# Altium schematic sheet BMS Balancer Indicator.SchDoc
size A4; SheetNumber: 2; SheetTotal: 2
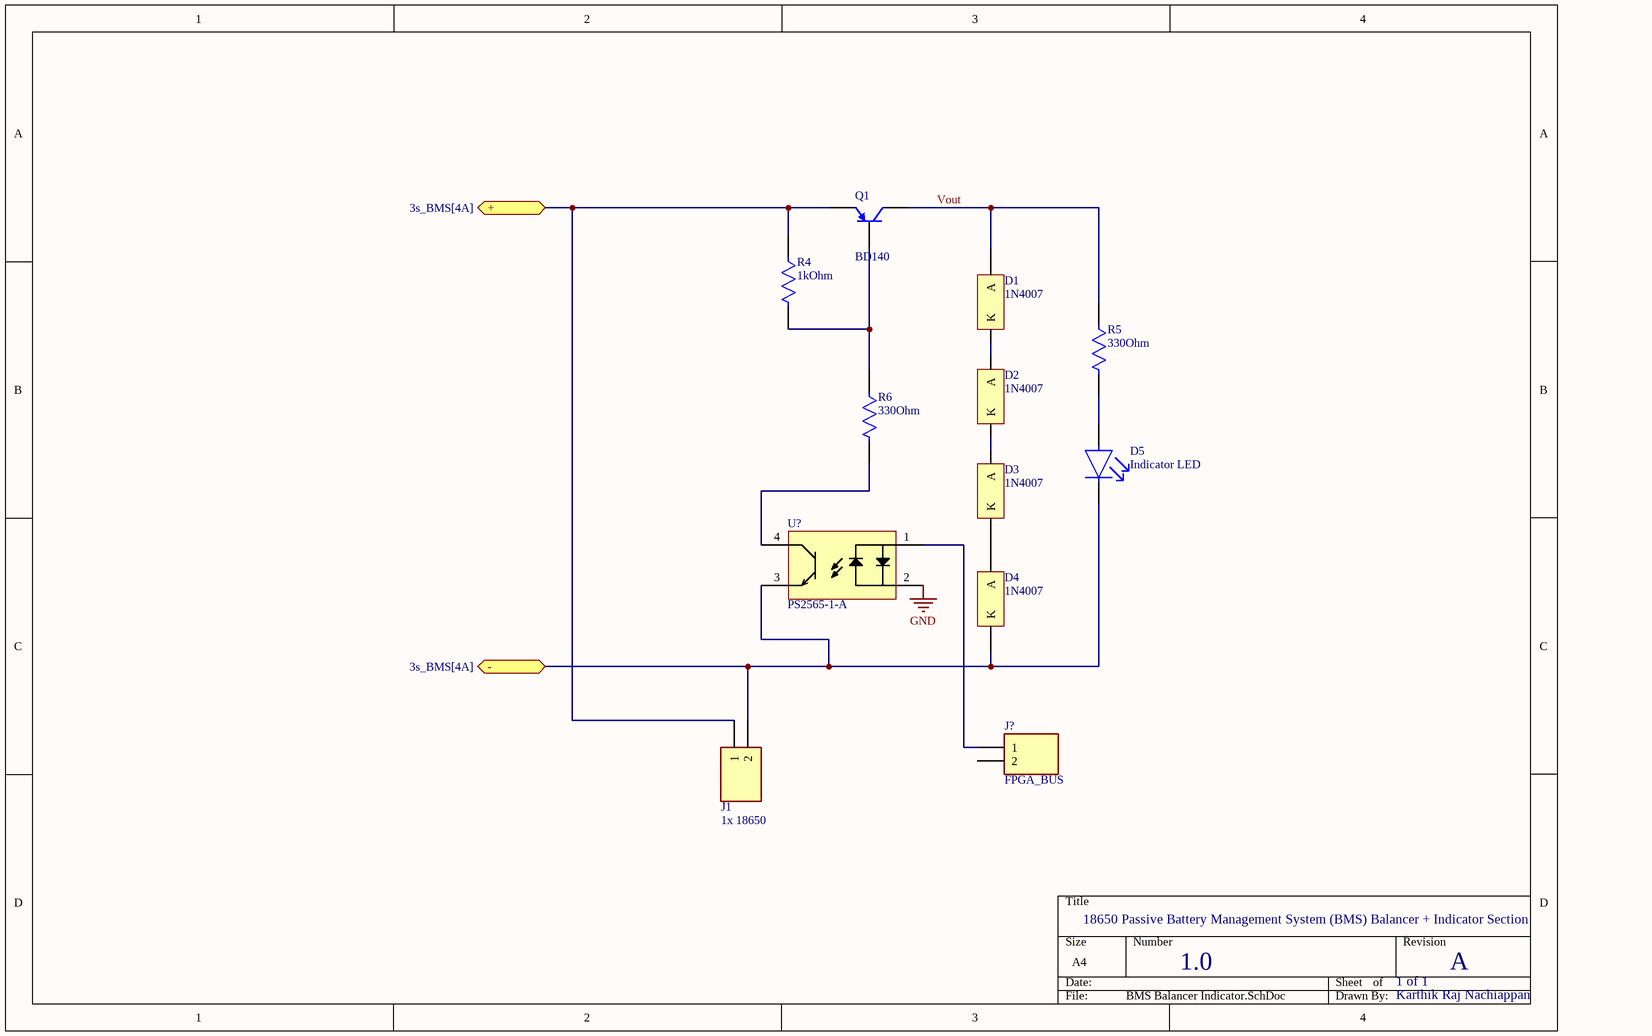
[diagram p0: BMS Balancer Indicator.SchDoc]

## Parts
D1  1N4007  [ONSC-AXIAL_LEAD-2-59-10_P]
D2  1N4007  [ONSC-AXIAL_LEAD-2-59-10_P]
D3  1N4007  [ONSC-AXIAL_LEAD-2-59-10_P]
D4  1N4007  [ONSC-AXIAL_LEAD-2-59-10_P]
D5  Indicator LED  [FP-HLMP-4700-MFG]
J1  1x 18650  [2828372]
J?  FPGA_BUS  [HDRV2W67P0X254_1X2_467X234X823P]
Q1  BD140  [ONSC-TO-225-3-77-09]
R4  1kOhm  [FP-MRS25-MFG]
R5  330Ohm  [FP-MRS25-MFG]
R6  330Ohm  [FP-MRS25-MFG]
U?  PS2565-1-A  [DIP762W50P254L460H455Q4B]

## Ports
+ (bidir, see 3s_BMS[4A]), - (bidir, see 3s_BMS[4A])

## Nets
GND: U?.2(Cathode)
+: J1.1 Q1.1(E) R4.1 ; port +
-: D4.1(K) D5.1(C) J1.2 U?.3(Emitter) ; port -
Vout: D1.2(A) Q1.2(C) R5.1
NetD1_1: D1.1(K) D2.2(A)
NetD2_1: D2.1(K) D3.2(A)
NetD3_1: D3.1(K) D4.2(A)
NetD5_2: D5.2(A) R5.2
NetJ?_1: J?.1 U?.1(Anode)
NetQ1_3: Q1.3(B) R4.2 R6.1
NetR6_2: R6.2 U?.4(Collector)

Not connected (* = marked no-connect by the designer): J? 2

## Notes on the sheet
- 18650 Passive Battery Management System (BMS) Balancer + Indicator Section
- 1.0
- 1 of 1
- A
- Karthik Raj Nachiappan

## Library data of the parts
D1-D4 = CMP-0902-00142-1: Standard Recovery Rectifier, 2-Pin Axial_Lead, Pb-Free, Bulk Bag; Manufacturer: On Semiconductor; IO(rec) Max (A): 1; IFSM Max (A): 30; VRRM Max (V): 1000
D5 = CMP-18399-000008-1: LED RED DIFFUSED T-1 3/4 T/H; Manufacturer: Broadcom; Luminous Intensity: 2.3mcd; Peak Emmision Wavelength: 635nm; Forward Voltage: 1.7V; Viewing Angle: 50°; Led Orientation: Straight; Reverse Voltage: 5V; Forward Current: 2mA; Power Dissipation: 14mW; Wavelength: 626nm
J1 = 282837-2: Connector; Manufacturer_Name: TE Connectivity
J? = 5-146277-2: Connector; Manufacturer_Name: TE Connectivity
Q1 = CMP-1048-00039-1: Plastic Medium-Power Silicon PNP Transistor, 3-Pin TO-225, Bulk Box; Manufacturer: On Semiconductor; IC Continuous (A): 1.5
R4-R6 = CMP-02408-000051-1: RES 1K OHM 0.6W 1% AXIAL; Power Rating: 600mW; Lead Diameter: 0.6mm; Voltage Rating (DC): 350V; Resistance: 1kR; Temperature Coefficient: 50ppm/°C
U? = CMP-00572-25674254-1: PS2565-1-A Optocoupler AC-IN 1-CH Transistor DC-OUT 4-Pin PDIP Magazine; Number of Elements: 1; Isolation Voltage: 5kV; Collector Emitter Voltage (VCEO): 300mV; Forward Current: 80mA; Output Current per Channel: 50mA; Output Voltage: 80V; Current Transfer Ratio: 400%; Forward Voltage: 1.4V; Rise Time: 3µs; Max Power Dissipation: 150mW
